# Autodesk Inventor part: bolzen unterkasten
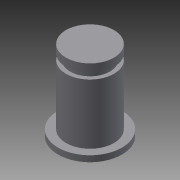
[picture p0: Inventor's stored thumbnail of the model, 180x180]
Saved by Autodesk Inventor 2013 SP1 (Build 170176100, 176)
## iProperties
Created: 2012-11
Part Number: bolzen unterkasten
Material: Allgemein
Document SubType Name: Modeling
Designer: s0536599
Density: 1 g/cm^3
Author: s0536599
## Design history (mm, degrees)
sketch "Skizze1"
  geometry: L1 (0, 0)-(6, 0); L2 (6, 0)-(6, 15); L3 (6, 15)-(5, 15); L4 (5, 15)-(5, 16.5); L5 (5, 16.5)-(6, 16.5); L6 (6, 16.5)-(6, 18.5); L7 (6, 18.5)-(0, 18.5); L8 (6, 0)-(8, 0); L9 (8, 0)-(8, -1.5); L10 (8, -1.5)-(0, -1.5); L11 (0, 18.5)-(0, -1.5); L12 (0, -5.5)-(0, 22.5) reference; L13 (9.6, 0)-(-1.6, 0) reference
  constraints: 22 end point, 5 parallel, 5 perpendicular, 1 horizontal
  dimensions: "d0" = 6 distance of L1.start L1.end; "d1" = 15 distance of L1.end L2.end; "d2" = 1 distance of L2.end L3.end; "d3" = 1.5 distance of L3.end L4.end; "d4" = 1 distance of L4.end L5.end; "d5" = 2 distance of L5.end L6.end; "d6" = 2 distance of L1.end L8.end; "d7" = 1.5 distance of L8.end L9.end
revolve "Umdrehung1" sketch "Skizze1" stored, may be unused: angle "d8" = 90 deg
node "Volumenkörper1"
